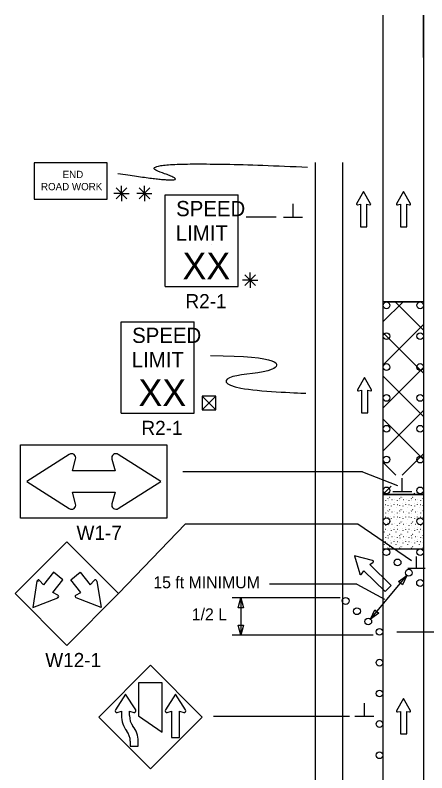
# Model space of a CAD drawing. Extents: x 16726 to 18482, y 5650 to 7013.
# Drawn here: x 16726.1 to 16969.3, y 6566.2 to 7013.5 of the extents above; entities that cross this region are included whole.
import ezdxf

# ---------------------------------------------------------------- set-up
doc = ezdxf.new("R2010")
doc.units = 0
for name, color, linetype in [('ALI_LEGAL_EX', 7, 'Continuous'), ('MT_SCRATCH_LEVEL_E', 7, 'Continuous'), ('PAVT_EDGE_EX', 7, 'Continuous'), ('TRAFFIC_SIGNS_PR', 7, 'Continuous'), ('TYPICAL_TEXT_DIMEN_PR', 7, 'Continuous')]:
    doc.layers.add(name, color=color, linetype=linetype)

msp = doc.modelspace()

# ---------------------------------------------------------------- linework, layer by layer
at = {"layer": 'ALI_LEGAL_EX'}
for p, q in [((16943.36, 7013.47), (16943.36, 6195.33)), ((16967.36, 7013.47), (16967.36, 6195.33)), ((16943.36, 6961.56), (16943.36, 6097.65)), ((16967.36, 6961.56), (16967.36, 6097.65))]:
    msp.add_line(p, q, dxfattribs=at)
for points in [[(16967.36, 6988.47), (16967.36, 7013.47)], [(16943.36, 6924.34), (16943.36, 6899.34)], [(16943.36, 6924.34), (16943.36, 6899.34)], [(16943.36, 6924.34), (16943.36, 6899.34)], [(16943.36, 6924.34), (16943.36, 6899.34)], [(16943.36, 6924.34), (16943.36, 6899.34)], [(16967.36, 6924.34), (16967.36, 6899.34)], [(16967.36, 6924.34), (16967.36, 6899.34)], [(16967.36, 6924.34), (16967.36, 6899.34)], [(16967.36, 6924.34), (16967.36, 6899.34)], [(16967.36, 6924.34), (16967.36, 6899.34)], [(16943.36, 6824.34), (16943.36, 6799.34)], [(16943.36, 6824.34), (16943.36, 6799.34)], [(16943.36, 6824.34), (16943.36, 6799.34)], [(16943.36, 6824.34), (16943.36, 6799.34)], [(16943.36, 6824.34), (16943.36, 6799.34)], [(16967.36, 6824.34), (16967.36, 6799.34)], [(16967.36, 6824.34), (16967.36, 6799.34)], [(16967.36, 6824.34), (16967.36, 6799.34)], [(16967.36, 6824.34), (16967.36, 6799.34)], [(16967.36, 6824.34), (16967.36, 6799.34)], [(16943.36, 6724.34), (16943.36, 6699.34)], [(16943.36, 6724.34), (16943.36, 6699.34)], [(16943.36, 6724.34), (16943.36, 6699.34)], [(16943.36, 6724.34), (16943.36, 6699.34)], [(16943.36, 6724.34), (16943.36, 6699.34)], [(16967.36, 6724.34), (16967.36, 6699.34)], [(16967.36, 6724.34), (16967.36, 6699.34)], [(16967.36, 6724.34), (16967.36, 6699.34)], [(16967.36, 6724.34), (16967.36, 6699.34)], [(16967.36, 6724.34), (16967.36, 6699.34)], [(16943.36, 6624.34), (16943.36, 6599.34)], [(16943.36, 6624.34), (16943.36, 6599.34)], [(16943.36, 6624.34), (16943.36, 6599.34)], [(16943.36, 6624.34), (16943.36, 6599.34)], [(16943.36, 6624.34), (16943.36, 6599.34)], [(16967.36, 6624.34), (16967.36, 6599.34)], [(16967.36, 6624.34), (16967.36, 6599.34)], [(16967.36, 6624.34), (16967.36, 6599.34)], [(16967.36, 6624.34), (16967.36, 6599.34)], [(16967.36, 6624.34), (16967.36, 6599.34)]]:
    msp.add_lwpolyline(points, dxfattribs=at)
at = {"layer": 'MT_SCRATCH_LEVEL_E'}
for p, q in [((16931.92, 6909.41), (16927.81, 6902.17)), ((16936.06, 6902.17), (16931.92, 6909.41)), ((16955.46, 6909.41), (16951.35, 6902.17)), ((16959.61, 6902.17), (16955.46, 6909.41)), ((16928.29, 6901.48), (16930.06, 6901.8)), ((16930.06, 6901.8), (16930.06, 6888.54)), ((16933.81, 6888.54), (16933.81, 6901.8)), ((16933.81, 6901.8), (16935.58, 6901.48)), ((16951.83, 6901.48), (16953.61, 6901.8)), ((16953.61, 6901.8), (16953.61, 6888.54)), ((16957.35, 6888.54), (16957.35, 6901.8)), ((16957.35, 6901.8), (16959.13, 6901.48)), ((16930.06, 6888.54), (16933.81, 6888.54)), ((16953.61, 6888.54), (16957.35, 6888.54)), ((16932.45, 6799.6), (16928.34, 6792.36)), ((16936.59, 6792.36), (16932.45, 6799.6)), ((16928.82, 6791.67), (16930.6, 6791.99)), ((16930.6, 6791.99), (16930.6, 6778.73)), ((16934.34, 6778.73), (16934.34, 6791.99)), ((16934.34, 6791.99), (16936.11, 6791.67)), ((16930.6, 6778.73), (16934.34, 6778.73)), ((16937.26, 6691.59), (16926.48, 6694.35)), ((16926.48, 6694.35), (16929.59, 6683.69)), ((16935.51, 6689.09), (16937.47, 6690.49)), ((16948.19, 6676.77), (16935.51, 6689.09)), ((16930.69, 6683.52), (16932.04, 6685.51)), ((16932.04, 6685.51), (16944.72, 6673.19)), ((16944.72, 6673.19), (16948.19, 6676.77)), ((16955.46, 6610.04), (16951.35, 6602.8)), ((16959.61, 6602.8), (16955.46, 6610.04)), ((16951.83, 6602.12), (16953.61, 6602.43)), ((16953.61, 6602.43), (16953.61, 6589.18)), ((16957.35, 6589.18), (16957.35, 6602.43)), ((16957.35, 6602.43), (16959.13, 6602.12)), ((16953.61, 6589.18), (16957.35, 6589.18))]:
    msp.add_line(p, q, dxfattribs=at)
for centre, radius, start, end in [((16928.21, 6901.94), 0.463, 150.4248, 279.9638), ((16935.65, 6901.94), 0.463, 260.0362, 29.7731), ((16951.76, 6901.94), 0.463, 150.4248, 279.9638), ((16959.2, 6901.94), 0.463, 260.0362, 29.7731), ((16928.74, 6792.13), 0.463, 150.4248, 279.9638), ((16936.18, 6792.13), 0.463, 260.0362, 29.7731), ((16937.09, 6690.99), 0.617, 305.8646, 75.6015), ((16930.18, 6683.87), 0.617, 196.2532, 325.7922), ((16951.76, 6602.58), 0.463, 150.4248, 279.9638), ((16959.2, 6602.58), 0.463, 260.0362, 29.7731)]:
    msp.add_arc(centre, radius, start, end, dxfattribs=at)
at = {"layer": 'PAVT_EDGE_EX'}
for p, q in [((16903.36, 6926.44), (16903.36, 6057.56)), ((16919.36, 6926.44), (16919.36, 6057.56)), ((16967.36, 6844.29), (16943.36, 6844.29)), ((16943.36, 6844.29), (16967.36, 6844.29)), ((16943.36, 6844.29), (16967.36, 6844.29)), ((16943.36, 6832.39), (16955.26, 6844.29)), ((16967.36, 6827.48), (16950.55, 6844.29)), ((16943.36, 6806.94), (16967.36, 6830.94)), ((16967.36, 6802.03), (16943.36, 6826.03)), ((16943.36, 6781.48), (16967.36, 6805.48)), ((16967.36, 6776.57), (16943.36, 6800.57)), ((16943.36, 6756.02), (16967.36, 6780.02)), ((16967.36, 6751.11), (16943.36, 6775.11)), ((16954.71, 6741.91), (16967.36, 6754.57)), ((16951.02, 6741.99), (16943.36, 6749.66)), ((16943.36, 6730.57), (16948.22, 6735.43)), ((16943.36, 6730.57), (16967.36, 6730.57)), ((16943.36, 6730.57), (16967.36, 6730.57)), ((16967.36, 6730.57), (16943.36, 6730.57)), ((16943.36, 6730.57), (16943.36, 6730.57)), ((16944.28, 6730.21), (16944.34, 6730.32)), ((16946.31, 6728.01), (16946.36, 6728.13)), ((16947.07, 6728.97), (16947.12, 6728.89)), ((16947.81, 6728.94), (16947.86, 6728.86)), ((16948.67, 6727.56), (16948.73, 6727.49)), ((16950.12, 6727.72), (16950.18, 6727.83)), ((16951.17, 6730.21), (16951.22, 6730.32)), ((16953.19, 6728.01), (16953.24, 6728.13)), ((16953.96, 6728.97), (16954.01, 6728.89)), ((16954.69, 6728.94), (16954.75, 6728.86)), ((16955.56, 6727.56), (16955.61, 6727.49)), ((16957.01, 6727.72), (16957.06, 6727.83)), ((16958.06, 6730.21), (16958.11, 6730.32)), ((16960.08, 6728.01), (16960.13, 6728.13)), ((16960.84, 6728.97), (16960.9, 6728.89)), ((16961.58, 6728.94), (16961.63, 6728.86)), ((16962.45, 6730.57), (16961.79, 6731.23)), ((16962.45, 6727.56), (16962.5, 6727.49)), ((16963.9, 6727.72), (16963.95, 6727.83)), ((16964.95, 6730.21), (16965, 6730.32)), ((16966.97, 6728.01), (16967.02, 6728.13)), ((16944.28, 6722.92), (16944.34, 6723.04)), ((16944.85, 6726.89), (16944.91, 6726.81)), ((16944.9, 6724.68), (16944.96, 6724.6)), ((16946.19, 6724.1), (16946.2, 6723.98)), ((16946.39, 6726.75), (16946.44, 6726.67)), ((16948.03, 6724.96), (16948.08, 6725.07)), ((16948.22, 6723.76), (16948.27, 6723.68)), ((16949.95, 6725.83), (16950, 6725.75)), ((16949.99, 6724.43), (16950.05, 6724.54)), ((16951.17, 6722.92), (16951.22, 6723.04)), ((16951.74, 6726.89), (16951.79, 6726.81)), ((16951.79, 6724.68), (16951.84, 6724.6)), ((16953.07, 6724.1), (16953.09, 6723.98)), ((16953.27, 6726.75), (16953.32, 6726.67)), ((16954.91, 6724.96), (16954.97, 6725.07)), ((16955.1, 6723.76), (16955.15, 6723.68)), ((16956.84, 6725.83), (16956.89, 6725.75)), ((16956.88, 6724.43), (16956.93, 6724.54)), ((16958.06, 6722.92), (16958.11, 6723.04)), ((16958.63, 6726.89), (16958.68, 6726.81)), ((16958.68, 6724.68), (16958.73, 6724.6)), ((16959.96, 6724.1), (16959.97, 6723.98)), ((16960.16, 6726.75), (16960.21, 6726.67)), ((16961.8, 6724.96), (16961.85, 6725.07)), ((16961.99, 6723.76), (16962.04, 6723.68)), ((16963.73, 6725.83), (16963.78, 6725.75)), ((16963.77, 6724.43), (16963.82, 6724.54)), ((16964.95, 6722.92), (16965, 6723.04)), ((16965.52, 6726.89), (16965.57, 6726.81)), ((16965.57, 6724.68), (16965.62, 6724.6)), ((16966.85, 6724.1), (16966.86, 6723.98)), ((16967.05, 6726.75), (16967.1, 6726.67)), ((16944.85, 6719.6), (16944.91, 6719.52)), ((16946.31, 6720.73), (16946.36, 6720.84)), ((16946.39, 6719.46), (16946.44, 6719.38)), ((16947.07, 6721.69), (16947.12, 6721.61)), ((16947.81, 6721.66), (16947.86, 6721.58)), ((16948.67, 6720.28), (16948.73, 6720.2)), ((16949.95, 6718.54), (16950, 6718.46)), ((16950.12, 6720.43), (16950.18, 6720.55)), ((16951.74, 6719.6), (16951.79, 6719.52)), ((16953.19, 6720.73), (16953.24, 6720.84)), ((16953.27, 6719.46), (16953.32, 6719.38)), ((16953.96, 6721.69), (16954.01, 6721.61)), ((16954.69, 6721.66), (16954.75, 6721.58)), ((16955.56, 6720.28), (16955.61, 6720.2)), ((16956.84, 6718.54), (16956.89, 6718.46)), ((16957.01, 6720.43), (16957.06, 6720.55)), ((16958.63, 6719.6), (16958.68, 6719.52)), ((16960.08, 6720.73), (16960.13, 6720.84)), ((16960.16, 6719.46), (16960.21, 6719.38)), ((16960.84, 6721.69), (16960.9, 6721.61)), ((16961.58, 6721.66), (16961.63, 6721.58)), ((16962.45, 6720.28), (16962.5, 6720.2)), ((16963.73, 6718.54), (16963.78, 6718.46)), ((16963.9, 6720.43), (16963.95, 6720.55)), ((16965.52, 6719.6), (16965.57, 6719.52)), ((16966.97, 6720.73), (16967.02, 6720.84)), ((16967.05, 6719.46), (16967.1, 6719.38)), ((16944.28, 6715.64), (16944.34, 6715.76)), ((16944.9, 6717.39), (16944.96, 6717.31)), ((16946.19, 6716.82), (16946.2, 6716.7)), ((16947.07, 6714.4), (16947.12, 6714.32)), ((16947.81, 6714.37), (16947.86, 6714.3)), ((16948.03, 6717.67), (16948.08, 6717.79)), ((16948.22, 6716.47), (16948.27, 6716.4)), ((16949.99, 6717.14), (16950.05, 6717.26)), ((16951.17, 6715.64), (16951.22, 6715.76)), ((16951.79, 6717.39), (16951.84, 6717.31)), ((16953.07, 6716.82), (16953.09, 6716.7)), ((16953.96, 6714.4), (16954.01, 6714.32)), ((16954.69, 6714.37), (16954.75, 6714.3)), ((16954.91, 6717.67), (16954.97, 6717.79)), ((16955.1, 6716.47), (16955.15, 6716.4)), ((16956.88, 6717.14), (16956.93, 6717.26)), ((16958.06, 6715.64), (16958.11, 6715.76)), ((16958.68, 6717.39), (16958.73, 6717.31)), ((16959.96, 6716.82), (16959.97, 6716.7)), ((16960.84, 6714.4), (16960.9, 6714.32)), ((16961.58, 6714.37), (16961.63, 6714.3)), ((16961.8, 6717.67), (16961.85, 6717.79)), ((16961.99, 6716.47), (16962.04, 6716.4)), ((16963.77, 6717.14), (16963.82, 6717.26)), ((16964.95, 6715.64), (16965, 6715.76)), ((16965.57, 6717.39), (16965.62, 6717.31)), ((16966.85, 6716.82), (16966.86, 6716.7)), ((16944.85, 6712.32), (16944.91, 6712.24)), ((16944.9, 6710.11), (16944.96, 6710.03)), ((16946.31, 6713.44), (16946.36, 6713.56)), ((16946.39, 6712.18), (16946.44, 6712.1)), ((16948.03, 6710.39), (16948.08, 6710.5)), ((16948.67, 6712.99), (16948.73, 6712.92)), ((16949.95, 6711.26), (16950, 6711.18)), ((16949.99, 6709.86), (16950.05, 6709.97)), ((16950.12, 6713.15), (16950.18, 6713.26)), ((16951.74, 6712.32), (16951.79, 6712.24)), ((16951.79, 6710.11), (16951.84, 6710.03)), ((16953.19, 6713.44), (16953.24, 6713.56)), ((16953.27, 6712.18), (16953.32, 6712.1)), ((16954.91, 6710.39), (16954.97, 6710.5)), ((16955.56, 6712.99), (16955.61, 6712.92)), ((16956.84, 6711.26), (16956.89, 6711.18)), ((16956.88, 6709.86), (16956.93, 6709.97)), ((16957.01, 6713.15), (16957.06, 6713.26)), ((16958.63, 6712.32), (16958.68, 6712.24)), ((16958.68, 6710.11), (16958.73, 6710.03)), ((16960.08, 6713.44), (16960.13, 6713.56)), ((16960.16, 6712.18), (16960.21, 6712.1)), ((16961.8, 6710.39), (16961.85, 6710.5)), ((16962.45, 6712.99), (16962.5, 6712.92)), ((16963.73, 6711.26), (16963.78, 6711.18)), ((16963.77, 6709.86), (16963.82, 6709.97)), ((16963.9, 6713.15), (16963.95, 6713.26)), ((16965.52, 6712.32), (16965.57, 6712.24)), ((16965.57, 6710.11), (16965.62, 6710.03)), ((16966.97, 6713.44), (16967.02, 6713.56)), ((16967.05, 6712.18), (16967.1, 6712.1)), ((16944.28, 6708.35), (16944.34, 6708.47)), ((16946.19, 6709.53), (16946.2, 6709.41)), ((16946.31, 6706.16), (16946.36, 6706.27)), ((16947.07, 6707.12), (16947.12, 6707.04)), ((16947.81, 6707.09), (16947.86, 6707.01)), ((16948.22, 6709.19), (16948.27, 6709.11)), ((16948.67, 6705.71), (16948.73, 6705.63)), ((16950.12, 6705.86), (16950.18, 6705.98)), ((16951.17, 6708.35), (16951.22, 6708.47)), ((16953.07, 6709.53), (16953.09, 6709.41)), ((16953.19, 6706.16), (16953.24, 6706.27)), ((16953.96, 6707.12), (16954.01, 6707.04)), ((16954.69, 6707.09), (16954.75, 6707.01)), ((16955.1, 6709.19), (16955.15, 6709.11)), ((16955.56, 6705.71), (16955.61, 6705.63)), ((16957.01, 6705.86), (16957.06, 6705.98)), ((16958.06, 6708.35), (16958.11, 6708.47)), ((16959.96, 6709.53), (16959.97, 6709.41)), ((16960.08, 6706.16), (16960.13, 6706.27)), ((16960.84, 6707.12), (16960.9, 6707.04)), ((16961.58, 6707.09), (16961.63, 6707.01)), ((16961.99, 6709.19), (16962.04, 6709.11)), ((16962.45, 6705.71), (16962.5, 6705.63)), ((16963.9, 6705.86), (16963.95, 6705.98)), ((16964.95, 6708.35), (16965, 6708.47)), ((16966.85, 6709.53), (16966.86, 6709.41)), ((16966.97, 6706.16), (16967.02, 6706.27)), ((16944.28, 6701.07), (16944.34, 6701.19)), ((16944.85, 6705.03), (16944.91, 6704.95)), ((16944.9, 6702.82), (16944.96, 6702.74)), ((16946.19, 6702.25), (16946.2, 6702.13)), ((16946.39, 6704.89), (16946.44, 6704.81)), ((16948.03, 6703.1), (16948.08, 6703.22)), ((16948.22, 6701.9), (16948.27, 6701.82)), ((16949.95, 6703.97), (16950, 6703.89)), ((16949.99, 6702.57), (16950.05, 6702.69)), ((16951.17, 6701.07), (16951.22, 6701.19)), ((16951.74, 6705.03), (16951.79, 6704.95)), ((16951.79, 6702.82), (16951.84, 6702.74)), ((16953.07, 6702.25), (16953.09, 6702.13)), ((16953.27, 6704.89), (16953.32, 6704.81)), ((16954.91, 6703.1), (16954.97, 6703.22)), ((16955.1, 6701.9), (16955.15, 6701.82)), ((16956.84, 6703.97), (16956.89, 6703.89)), ((16956.88, 6702.57), (16956.93, 6702.69)), ((16958.06, 6701.07), (16958.11, 6701.19)), ((16958.63, 6705.03), (16958.68, 6704.95)), ((16958.68, 6702.82), (16958.73, 6702.74)), ((16959.96, 6702.25), (16959.97, 6702.13)), ((16960.16, 6704.89), (16960.21, 6704.81)), ((16961.8, 6703.1), (16961.85, 6703.22)), ((16961.99, 6701.9), (16962.04, 6701.82)), ((16963.73, 6703.97), (16963.78, 6703.89)), ((16963.77, 6702.57), (16963.82, 6702.69)), ((16964.95, 6701.07), (16965, 6701.19)), ((16965.52, 6705.03), (16965.57, 6704.95)), ((16965.57, 6702.82), (16965.62, 6702.74)), ((16966.85, 6702.25), (16966.86, 6702.13)), ((16967.05, 6704.89), (16967.1, 6704.81)), ((16943.36, 6698.51), (16967.36, 6698.51)), ((16943.36, 6698.51), (16967.36, 6698.51)), ((16946.31, 6698.87), (16946.36, 6698.99)), ((16947.07, 6699.83), (16947.12, 6699.76)), ((16947.81, 6699.8), (16947.86, 6699.73)), ((16950.12, 6698.57), (16950.18, 6698.69)), ((16953.19, 6698.87), (16953.24, 6698.99)), ((16953.96, 6699.83), (16954.01, 6699.76)), ((16954.69, 6699.8), (16954.75, 6699.73)), ((16957.01, 6698.57), (16957.06, 6698.69)), ((16960.08, 6698.87), (16960.13, 6698.99)), ((16960.84, 6699.83), (16960.9, 6699.76)), ((16961.58, 6699.8), (16961.63, 6699.73)), ((16963.9, 6698.57), (16963.95, 6698.69)), ((16966.97, 6698.87), (16967.02, 6698.99))]:
    msp.add_line(p, q, dxfattribs=at)
at = {"layer": 'TRAFFIC_SIGNS_PR'}
for p, q in [((16814.7, 6907.31), (16857.9, 6907.31)), ((16814.7, 6853.31), (16814.7, 6907.31)), ((16857.9, 6853.31), (16857.9, 6907.31)), ((16814.7, 6853.31), (16857.9, 6853.31)), ((16788.71, 6832.49), (16831.91, 6832.49)), ((16788.71, 6778.49), (16788.71, 6832.49)), ((16831.91, 6778.49), (16831.91, 6832.49)), ((16788.71, 6778.49), (16831.91, 6778.49)), ((16756.66, 6702.53), (16726.11, 6671.98)), ((16787.2, 6671.98), (16756.66, 6702.53)), ((16739.88, 6679.18), (16739.01, 6679.33)), ((16726.11, 6671.98), (16756.66, 6641.44)), ((16750.92, 6670.33), (16751.25, 6669.49)), ((16756.66, 6641.44), (16787.2, 6671.98)), ((16806.08, 6629.67), (16775.53, 6599.12)), ((16836.63, 6599.12), (16806.08, 6629.67)), ((16775.53, 6599.12), (16806.08, 6568.58)), ((16806.08, 6568.58), (16836.63, 6599.12))]:
    msp.add_line(p, q, dxfattribs=at)
for points in [[(16737.31, 6904.77), (16780.51, 6904.77), (16780.51, 6926.36), (16737.31, 6926.36)], [(16815.73, 6716.57), (16729.33, 6716.57), (16729.33, 6759.77), (16815.73, 6759.77)], [(16798.98, 6619.3), (16798.98, 6599.78), (16812.94, 6590.09), (16812.94, 6619.3)]]:
    msp.add_lwpolyline(points, close=True, dxfattribs=at)
for points in [[(16758.04, 6754.15), (16732.93, 6738.17), (16758.04, 6722.19)], [(16783.24, 6751.35), (16785.12, 6744.47), (16759.93, 6744.47), (16761.82, 6751.35)], [(16787.02, 6722.19), (16812.13, 6738.17), (16787.02, 6754.15)], [(16761.82, 6724.98), (16759.93, 6731.87), (16785.12, 6731.87), (16783.24, 6724.98)], [(16751.35, 6671.11), (16748.34, 6672.72), (16754.28, 6680.1), (16748.73, 6684.56), (16742.8, 6677.18), (16740.54, 6679.76)], [(16761.96, 6671.11), (16764.97, 6672.72), (16759.04, 6680.1), (16764.58, 6684.56), (16770.51, 6677.18), (16772.77, 6679.76)], [(16739.01, 6679.33), (16736.48, 6663.7), (16751.25, 6669.49)], [(16774.3, 6679.33), (16776.84, 6663.7), (16762.07, 6669.49)], [(16797.3, 6603.29), (16791.31, 6612.71), (16785.31, 6603.29)], [(16826.8, 6603.29), (16820.81, 6612.71), (16814.82, 6603.29)], [(16786.36, 6601.87), (16788.94, 6602.58), (16788.94, 6600.07)], [(16793.66, 6599.95), (16793.66, 6602.58), (16796.25, 6601.87)], [(16815.87, 6601.87), (16818.45, 6602.58), (16818.45, 6587.06), (16823.17, 6587.06), (16823.17, 6602.58), (16825.76, 6601.87)], [(16794.08, 6584.94), (16794.08, 6581.95), (16798.8, 6581.95), (16798.8, 6584.94)]]:
    msp.add_lwpolyline(points, dxfattribs=at)
for centre in [(16945.46, 6842.17), (16965.33, 6842.17), (16945.46, 6823.96), (16965.33, 6823.96), (16945.46, 6805.74), (16965.33, 6805.74), (16945.46, 6787.53), (16965.33, 6787.53), (16945.46, 6769.31), (16965.33, 6769.31), (16945.46, 6751.1), (16965.33, 6751.1), (16945.46, 6732.88), (16965.33, 6732.88), (16945.46, 6714.67), (16965.33, 6714.67), (16945.34, 6696.47), (16965.33, 6696.46), (16951.99, 6690.4), (16958.64, 6684.33), (16965.29, 6678.27), (16921.35, 6667.64), (16928, 6661.57), (16934.65, 6655.5), (16941.29, 6649.44), (16941.29, 6649.44), (16941.29, 6631.22), (16941.29, 6613.01), (16941.29, 6595.01), (16941.29, 6576.58)]:
    msp.add_circle(centre, 2, dxfattribs=at)
for centre, radius, start, end in [((16759.39, 6752.02), 2.52, 344.6731, 122.4696), ((16785.67, 6752.02), 2.52, 57.5304, 195.3269), ((16759.39, 6724.31), 2.52, 237.5304, 15.3269), ((16785.67, 6724.32), 2.52, 164.6928, 302.4524), ((16739.88, 6679.17), 0.885, 41.8659, 170.0393), ((16773.43, 6679.17), 0.885, 9.9607, 138.1341), ((16750.92, 6670.33), 0.9, 291.4077, 61.1792), ((16762.4, 6670.33), 0.9, 118.8208, 248.5923), ((16786.11, 6602.78), 0.945, 147.5204, 285.3986), ((16796.5, 6602.78), 0.947, 254.6828, 32.2708), ((16807.26, 6609.63), 11.81, 212.4569, 212.4665), ((16815.62, 6602.78), 0.946, 147.5497, 285.3316), ((16826.01, 6602.78), 0.943, 254.6778, 32.4665), ((16836.77, 6609.63), 11.81, 212.4569, 212.4665), ((16803.1, 6599.66), 14.17, 178.3293, 218.5427), ((16803.1, 6599.66), 9.45, 178.1936, 218.5465), ((16781.85, 6600.33), 11.81, 358.1894, 0.0048), ((16793.13, 6590.48), 11.81, 74.68, 74.6808), ((16784.63, 6584.94), 14.17, 0, 38.5422), ((16784.63, 6584.94), 9.45, 0, 38.5457)]:
    msp.add_arc(centre, radius, start, end, dxfattribs=at)
msp.add_open_spline([(16786.85, 6920.02), (16837.26, 6912.2), (16788.08, 6928.73), (16898.87, 6923.78)], degree=2, dxfattribs=at)
at = {"layer": 'TYPICAL_TEXT_DIMEN_PR'}
for p, q in [((16785.76, 6911.44), (16792.14, 6905.06)), ((16792.14, 6911.44), (16785.76, 6905.06)), ((16788.95, 6908.25), (16788.95, 6912.71)), ((16799.27, 6911.44), (16805.64, 6905.06)), ((16805.64, 6911.44), (16799.27, 6905.06)), ((16802.45, 6908.25), (16802.45, 6912.71)), ((16788.95, 6908.25), (16784.42, 6908.25)), ((16788.95, 6908.25), (16792.14, 6908.25)), ((16788.95, 6908.25), (16793.42, 6908.25)), ((16788.95, 6908.25), (16788.95, 6903.75)), ((16802.45, 6908.25), (16797.92, 6908.25)), ((16802.45, 6908.25), (16805.64, 6908.25)), ((16802.45, 6908.25), (16806.93, 6908.25)), ((16802.45, 6908.25), (16802.45, 6903.75)), ((16890.23, 6894.29), (16890.23, 6902.08)), ((16880.36, 6894.29), (16862.46, 6894.29)), ((16884.61, 6894.29), (16895.86, 6894.29)), ((16861.73, 6860.26), (16868.1, 6853.88)), ((16868.1, 6860.26), (16861.73, 6853.88)), ((16864.92, 6857.07), (16864.92, 6861.53)), ((16864.92, 6857.07), (16860.39, 6857.07)), ((16864.92, 6857.07), (16868.1, 6857.07)), ((16864.92, 6857.07), (16869.4, 6857.07)), ((16864.92, 6857.07), (16864.92, 6852.57)), ((16836.58, 6788.53), (16844.58, 6780.53)), ((16836.58, 6780.53), (16844.58, 6788.53)), ((16931.31, 6743.86), (16825.22, 6743.86)), ((16931.31, 6743.86), (16951.88, 6735.74)), ((16954.76, 6732.25), (16954.76, 6740.04)), ((16949.14, 6732.25), (16960.39, 6732.25)), ((16826.75, 6713.19), (16787.2, 6671.98)), ((16826.75, 6713.19), (16928.43, 6713.19)), ((16928.43, 6713.19), (16960.23, 6691.55)), ((16963.19, 6686.9), (16963.19, 6693.91)), ((16936.03, 6656.95), (16957.47, 6682.72)), ((16952.51, 6679.22), (16957.47, 6682.72)), ((16957.47, 6682.72), (16954.92, 6677.21)), ((16968.25, 6686.9), (16958.12, 6686.9)), ((16953.72, 6678.21), (16952.51, 6679.22)), ((16927.87, 6677.49), (16876.4, 6677.49)), ((16927.87, 6677.49), (16944.28, 6668.65)), ((16954.92, 6677.21), (16953.72, 6678.21)), ((16918.08, 6669.41), (16854.36, 6669.41)), ((16857.79, 6663.55), (16859.36, 6669.41)), ((16859.36, 6669.41), (16860.93, 6663.55)), ((16859.36, 6669.41), (16859.36, 6647.44)), ((16859.36, 6663.55), (16857.79, 6663.55)), ((16860.93, 6663.55), (16859.36, 6663.55)), ((16936.03, 6656.95), (16938.57, 6662.46)), ((16940.98, 6660.45), (16936.03, 6656.95)), ((16938.57, 6662.46), (16939.78, 6661.46)), ((16939.78, 6661.46), (16940.98, 6660.45)), ((16859.36, 6647.44), (16857.79, 6653.3)), ((16857.79, 6653.3), (16859.36, 6653.3)), ((16859.36, 6653.3), (16860.93, 6653.3)), ((16860.93, 6653.3), (16859.36, 6647.44)), ((16937.53, 6647.44), (16854.36, 6647.44)), ((16951.51, 6649.44), (17056.36, 6649.44)), ((16932.4, 6599.44), (16932.4, 6607.22)), ((16923.57, 6599.44), (16843.29, 6599.44)), ((16938.02, 6599.44), (16926.77, 6599.44))]:
    msp.add_line(p, q, dxfattribs=at)
msp.add_lwpolyline([(16836.58, 6788.53), (16836.58, 6780.53), (16844.58, 6780.53), (16844.58, 6788.53)], close=True, dxfattribs=at)
for points, degree in [([(16842.09, 6877.99), (16842.1, 6877.99), (16842.11, 6877.99), (16842.11, 6877.99)], 2), ([(16841.47, 6812.46), (16883.68, 6812.46), (16883.68, 6801.71), (16848.77, 6801.71), (16848.77, 6792.05), (16891.63, 6790.53), (16897.89, 6790.27)], 3)]:
    msp.add_open_spline(points, degree=degree, dxfattribs=at)

# ---------------------------------------------------------------- texts
at = {"layer": 'TRAFFIC_SIGNS_PR'}
for s, height, p in [('END', 4.31, (16754.18, 6917.29)), ('ROAD WORK', 4.31, (16741.37, 6910.1)), ('SPEED', 9, (16821.19, 6894.78)), ('LIMIT', 9, (16821.01, 6880.38)), ('XX', 15.785, (16824.96, 6857.54)), ('R2-1', 8.37, (16826.72, 6840.44)), ('SPEED', 9, (16795.2, 6819.96)), ('LIMIT', 9, (16795.01, 6805.56)), ('XX', 15.785, (16798.96, 6782.72)), ('R2-1', 8.37, (16800.72, 6765.62)), ('W1-7', 8.37, (16762.36, 6703.7)), ('W12-1', 8.37, (16743.92, 6628.57))]:
    msp.add_text(s, height=height, dxfattribs=at).set_placement(p)
at = {"layer": 'TYPICAL_TEXT_DIMEN_PR'}
for s, p in [('15 ft MINIMUM', (16807.72, 6675.12)), ('1/2 L', (16830.43, 6656.25))]:
    msp.add_text(s, height=7, dxfattribs=at).set_placement(p)

doc.saveas('drawing.dxf')
